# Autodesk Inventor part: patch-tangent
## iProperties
Created: 2004-05
Part Number: patch-tangent
Document SubType Name: Modeling
Designer: CADCIM Technologies
Manufacturer: Standard
Standards Organization: Custom
Author: CADCIM Technologies
